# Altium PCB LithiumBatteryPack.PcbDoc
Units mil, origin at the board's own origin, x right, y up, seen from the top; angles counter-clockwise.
Board outline 15381.26 x 1815 mil, 2 copper layers (Top Layer, Bottom Layer); 16 components, 7 nets, 68 pads, 0 vias.
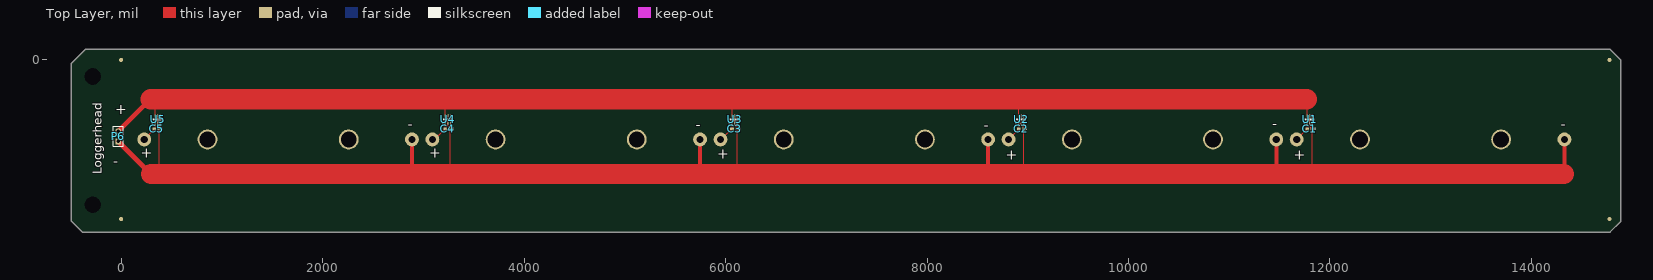
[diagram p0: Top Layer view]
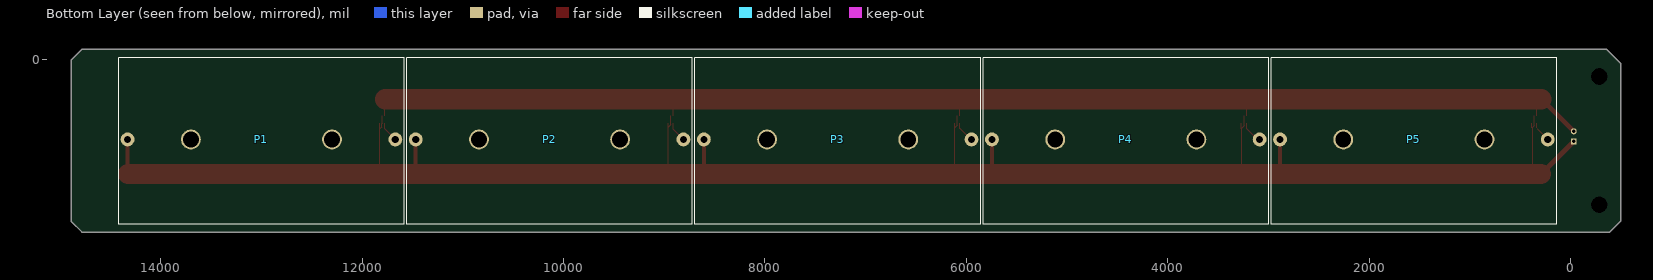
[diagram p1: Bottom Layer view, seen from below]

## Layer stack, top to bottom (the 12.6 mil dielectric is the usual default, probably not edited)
Top Solder: solder mask 0.4, Solder Resist, Dk 3.5
Top Layer: signal copper 1.4
Dielectric 1: dielectric 12.6, FR-4, Dk 4.8
Bottom Layer: signal copper 1.4
Bottom Solder: solder mask 0.4, Solder Resist, Dk 3.5

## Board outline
-385.59,-1710 -495,-1600.59 -495,-35.59 -354.41,105 14779.41,105 14886.26,-1.85 14886.26,-1604.33 14780.59,-1710

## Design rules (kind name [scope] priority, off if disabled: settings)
Clearance [All] p1: gap=10
PolygonConnect [All] p1: connectstyle=Relief reliefconductorwidth=10 reliefentries=4 polygonreliefangle="90 Angle" airgapwidth=10
RoutingVias [All] p1: holewidth=28 width=50 viastyle="Through Hole" minholewidth=28 minwidth=50 maxholewidth=28 maxwidth=50
SolderMaskExpansion [All] p1: expansion=4
Width [All] p1: maxlimit=200 minlimit=10 preferedwidth=10
29 further rules are at their usual default settings.

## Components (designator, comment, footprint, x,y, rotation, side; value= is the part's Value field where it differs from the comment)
C1 "1uF" 0402 11799.41,-685.59 r180 top
C2 "1uF" 0402 8934.41,-685.59 r180 top
C3 "1uF" 0402 6089.41,-685.59 r180 top
C4 "1uF" 0402 3243.82,-685.59 r180 top
C5 "1uF" 0402 354.41,-685.59 r180 top
P1 "D-cell" Battery-D 12998.23,-790 r0 bottom
P2 "D-cell" Battery-D 10138.23,-790 r0 bottom
P3 "D-cell" Battery-D 7278.23,-790 r0 bottom
P4 "D-cell" Battery-D 4418.23,-790 r0 bottom
P5 "D-cell" Battery-D 1558.23,-790 r0 bottom
P6 "Header 2" HDR1X2 -28.74,-810 r90 top
U1 "LM66100" SC-70-6 11800,-590.59 r90 top
U2 "LM66100" SC-70-6 8935,-590.59 r90 top
U3 "LM66100" SC-70-6 6090,-590.59 r90 top
U4 "LM66100" SC-70-6 3244.41,-590.59 r90 top
U5 "LM66100" SC-70-6 364.41,-590.59 r90 top

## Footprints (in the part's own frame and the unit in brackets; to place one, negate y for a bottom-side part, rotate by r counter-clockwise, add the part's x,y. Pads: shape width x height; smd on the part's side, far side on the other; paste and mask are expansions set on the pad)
0402 [mm] "Chip Capacitor; Body 1.0 x 0.5 mm (LxW typ)"
  rect 0.9x0.7 smd: 1(-0.65,0) 2(0.65,0)
  silkscreen extent -1.4,-0.25 -1.4,0.25
Battery-D [mm] "Bulgin BX0037"
  round 3.5 hole 1.8: 0(-33.75,0) 1(33.75,0)
  round 5 hole 4: 2(-17.8,0) 3(17.8,0)
  silkscreen extent -36.02,-20.55 35.98,21.35
HDR1X2 [mm] "Connector; Header; 2 Position"
  rect 1.5x1.5 hole 0.9: 1(0,0)
  round 1.5 hole 0.9: 2(2.54,0)
  silkscreen extent -1.27,-1.27 3.81,1.27
SC-70-6 [mm] "SOT23, 6-Leads, Body 2.00x2.10mm, Pitch 0.65mm, IPC Medium Density"
  rect 0.9x0.35 smd: 1(-0.95,0.65) 2(-0.95,0) 3(-0.95,-0.65) 4(0.95,-0.65) 5(0.95,0) 6(0.95,0.65)
  silkscreen extent -1.07,-1.1 0.1,1.5, body extent -0.7,-1.07 0.7,1.08, height 1.1

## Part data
C1 C2 C3 C4 C5: library part C0402, "Ceramic Chip Capacitor - Standard"
P1 P2 P3 P4 P5: library part Battery-D
P6: "Header, 2-Pin"

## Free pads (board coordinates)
  round 40 smd paste-20 mask+5: 0(0,-1580.59) 0(0,-0.59) 0(14775,-1580.59) 0(14775,-0.59)
  round 60 hole 165: 4(-280,-1440) 4(-280,-165)

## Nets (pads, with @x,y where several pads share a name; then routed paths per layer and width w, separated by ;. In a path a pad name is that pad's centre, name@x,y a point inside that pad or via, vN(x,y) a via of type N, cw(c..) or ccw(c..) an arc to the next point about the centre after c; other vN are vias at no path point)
GND: C1.1 C2.1 C3.1 C4.1 C5.1 P1.1 P2.1 P3.1 P4.1 P5.1 P6.1 U1.2 U1.3 U1.5 U2.2 U2.3 U2.5 U3.2 U3.3 U3.5 U4.2 U4.3 U4.5 U5.2 U5.3 U5.5 | length 19332.3
  Top Layer w10: U5.5 U5.2 364.41,-655.59 380,-671.18 C5.1 380,-1120.59 ; C5.1@390,-675.59 U5.3 ; U4.5 U4.2 3244.41,-655 3269.41,-680 C4.1 3269.41,-1130.59 ; C4.1@3270,-685 U4.3 ; U3.5 U3.2 6090,-650.59 C3.1@6115.59,-676.18 ; 6115,-1130 C3.1 ; C3.1@6115.59,-685 C3.1@6115.59,-676.18 ; U3.3 C3.1@6115.59,-676.18 ; U2.2 8935,-645.59 8960,-670.59 C2.1 8960,-1135 ; U2.2@8935,-625.59 U2.5 ; C2.1@8960.59,-685 U2.3 ; U1.5 U1.2 11806.53,-634.53 11806.53,-667.13 C1.1 11825,-1135 ; C1.1@11825.59,-685 U1.3
  Top Layer w40: 2886.97,-1103.03 P5.1 ; 5746.97,-1121.97 P4.1 ; 8606.97,-1116.97 P3.1 ; 11466.97,-1128.03 P2.1 ; 14326.97,-1129.88 P1.1
  Top Layer w50: P6.1 296.26,-1135
  Top Layer w200: 296.26,-1135 14321.85,-1135
NetC1_2: C1.2 P1.0 U1.1 | length 204.6
  Top Layer w10: P1.0 11773.82,-685.67 C1.2 U1.1@11773.82,-628.58
NetC2_2: C2.2 P2.0 U2.1 | length 202.6
  Top Layer w10: P2.0 8908.82,-690.67 C2.2 U2.1@8908.82,-628.58
NetC3_2: C3.2 P3.0 U3.1 | length 214.6
  Top Layer w10: P3.0 5959.41,-790 C3.2 ; C3.2@6064.41,-685 U3.1
NetC4_2: C4.2 P4.0 U4.1 | length 229.8
  Top Layer w10: P4.0 3113.82,-790 C4.2 3218.82,-685 U4.1
NetC5_2: C5.2 P5.0 U5.1 | length 193.2
  Top Layer w10: P5.0 328.82,-690.67 C5.2 ; C5.2@338.82,-675.59 U5.1
POW: P6.2 U1.6 U2.6 U3.6 U4.6 U5.6 | length 12717.6
  Top Layer w10: U5.6 338.82,-396.89 ; U4.6 3218.82,-395.12 ; U3.6 6064.41,-395.71 ; U2.6 8909.41,-395.71 ; U1.6 11774.41,-395.71
  Top Layer w50: P6.2 289.96,-391.3
  Top Layer w200: 289.96,-391.3 11770,-391.3
pads on no net: P1.2 P1.3 P2.2 P2.3 P3.2 P3.3 P4.2 P4.3 P5.2 P5.3 U1.4 U2.4 U3.4 U4.4 U5.4

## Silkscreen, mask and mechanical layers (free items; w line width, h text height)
Top Overlay:
  text "+" at -58.74,-540.59 h100
  text "-" at 11425,-685.59 h100
  text "-" at 2845,-690.59 h100
  text "-" at 14290,-690.59 h100
  text "-" at 5705,-695.59 h100
  text "-" at 8565,-700.59 h100
  text "+" at 195,-970.59 h100
  text "+" at 3060,-970.59 h100
  text "+" at 5920,-980.59 h100
  text "+" at 8780,-990.59 h100
  text "+" at 11640,-990.59 h100
  text "-" at -78.74,-1055.59 h100
  text "Loggerhead" at -165,-1135 h150 r90
Mechanical 1:
  the board outline again, w10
